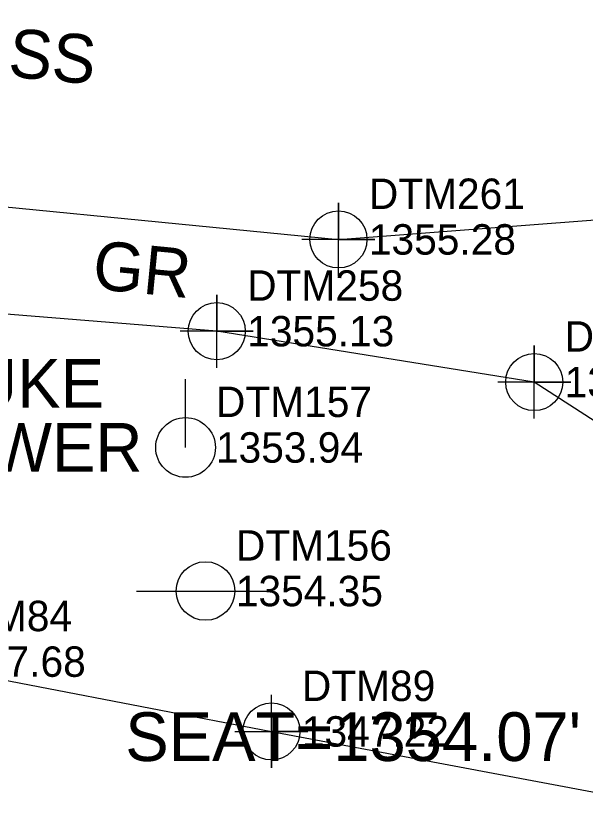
# Model space of a CAD drawing. Extents: x 1251492 to 1253015, y 859607 to 860610.
# Drawn here: x 1251972.9 to 1252019.6, y 860040 to 860105 of the extents above; entities that cross this region are included whole.
import ezdxf

# ---------------------------------------------------------------- set-up
doc = ezdxf.new("R2010")
doc.units = 0
for name, color, linetype in [('Exist Hydro Jurisdictional Stream or Body of Water', 7, 'Continuous'), ('Exist Hydro Stream or Body of Water Cogo Elevation', 7, 'Continuous'), ('Exist Hydro Stream or Body of Water Cogo Number', 7, 'Continuous'), ('Exist Hydro Stream or Body of Water Cogo Point CELL', 7, 'Continuous'), ('Exist Roads Soil', 7, 'Continuous'), ('Exist Roads Soil Cogo Elevation', 7, 'Continuous'), ('Exist Roads Soil Cogo Number', 7, 'Continuous'), ('Exist Roads Soil Cogo Point CELL', 7, 'Continuous'), ('Exist Roads Soil Text', 7, 'Continuous'), ('Exist Structure Major Bridge Seat Top Elevation', 7, 'Continuous'), ('Exist Utilities Power Pole CELL', 7, 'Continuous'), ('Exist Utilities Power Pole Cogo Elevation', 7, 'Continuous'), ('Exist Utilities Power Pole Cogo Number', 7, 'Continuous'), ('Exist Utilities Power Pole Text', 7, 'Continuous'), ('Exist Utilities Telephone Pole CELL', 7, 'Continuous'), ('Exist Utilities Telephone Pole Cogo Elevation', 7, 'Continuous'), ('Exist Utilities Telephone Pole Cogo Number', 7, 'Continuous'), ('Exist Vegetation Woods Line Text', 7, 'Continuous')]:
    doc.layers.add(name, color=color, linetype=linetype)

msp = doc.modelspace()

# ---------------------------------------------------------------- linework, layer by layer
at = {"layer": 'Exist Hydro Jurisdictional Stream or Body of Water'}
msp.add_lwpolyline([(1251931.145, 860058.535), (1251964.012, 860051.945), (1251993.851, 860046.208), (1252023.877, 860040.562), (1252026.116, 860039.985)], dxfattribs=at)
at = {"layer": 'Exist Hydro Stream or Body of Water Cogo Point CELL'}
msp.add_lwpolyline([(1251990.851, 860046.208), (1251996.851, 860046.208), (1251993.851, 860046.208), (1251993.851, 860043.208), (1251993.851, 860049.208)], dxfattribs=at)
msp.add_circle((1251993.851, 860046.208), 2.344, dxfattribs=at)
at = {"layer": 'Exist Roads Soil'}
for points in [[(1251956.92, 860090.785), (1251999.355, 860086.635), (1252028.297, 860088.86), (1252043.486, 860095.855), (1252053.212, 860097.101)], [(1252027.154, 860067.333), (1252015.44, 860074.915), (1251989.358, 860079.095), (1251956.453, 860081.754)]]:
    msp.add_lwpolyline(points, dxfattribs=at)
at = {"layer": 'Exist Roads Soil Cogo Point CELL'}
for points in [[(1251999.355, 860083.635), (1251999.355, 860089.635), (1251999.355, 860086.635), (1252002.355, 860086.635), (1251996.355, 860086.635)], [(1251989.358, 860076.095), (1251989.358, 860082.095), (1251989.358, 860079.095), (1251992.358, 860079.095), (1251986.358, 860079.095)], [(1252015.44, 860071.915), (1252015.44, 860077.915), (1252015.44, 860074.915), (1252018.44, 860074.915), (1252012.44, 860074.915)]]:
    msp.add_lwpolyline(points, dxfattribs=at)
for centre in [(1251999.355, 860086.635), (1251989.358, 860079.095), (1252015.44, 860074.915)]:
    msp.add_circle(centre, 2.344, dxfattribs=at)
at = {"layer": 'Exist Utilities Power Pole CELL'}
for q in [(1251986.794, 860075.165), (1251986.794, 860069.54)]:
    msp.add_line((1251986.794, 860069.54), q, dxfattribs=at)
msp.add_circle((1251986.794, 860069.54), 2.45, dxfattribs=at)
at = {"layer": 'Exist Utilities Telephone Pole CELL'}
for p, q in [((1251982.755, 860057.745), (1251994.093, 860057.745)), ((1251988.43, 860057.745), (1251988.43, 860057.745))]:
    msp.add_line(p, q, dxfattribs=at)
msp.add_circle((1251988.43, 860057.745), 2.407, dxfattribs=at)

# ---------------------------------------------------------------- texts
at = {"layer": 'Exist Hydro Stream or Body of Water Cogo Elevation'}
for s, p in [('1347.68', (1251966.512, 860050.695)), ('1347.22', (1251996.351, 860044.958))]:
    msp.add_text(s, height=2.5, dxfattribs=at).set_placement(p)
at = {"layer": 'Exist Hydro Stream or Body of Water Cogo Number'}
for s, p in [('DTM84', (1251966.512, 860054.445)), ('DTM89', (1251996.351, 860048.708))]:
    msp.add_text(s, height=2.5, dxfattribs=at).set_placement(p)
at = {"layer": 'Exist Roads Soil Cogo Elevation'}
for s, p in [('1355.28', (1252001.855, 860085.385)), ('1355.13', (1251991.858, 860077.845)), ('1356.25', (1252017.94, 860073.665))]:
    msp.add_text(s, height=2.5, dxfattribs=at).set_placement(p)
at = {"layer": 'Exist Roads Soil Cogo Number'}
for s, p in [('DTM261', (1252001.855, 860089.135)), ('DTM258', (1251991.858, 860081.595)), ('DTM257', (1252017.94, 860077.415))]:
    msp.add_text(s, height=2.5, dxfattribs=at).set_placement(p)
at = {"layer": 'Exist Roads Soil Text'}
msp.add_text('GR', height=4, rotation=354.41443, dxfattribs=at).set_placement((1251979.052, 860082.592))
at = {"layer": 'Exist Structure Major Bridge Seat Top Elevation'}
msp.add_text("SEAT=1354.07'", height=4, dxfattribs=at).set_placement((1251981.841, 860043.779))
at = {"layer": 'Exist Utilities Power Pole Cogo Elevation'}
msp.add_text('1353.94', height=2.5, dxfattribs=at).set_placement((1251989.294, 860068.29))
at = {"layer": 'Exist Utilities Power Pole Cogo Number'}
msp.add_text('DTM157', height=2.5, dxfattribs=at).set_placement((1251989.294, 860072.04))
at = {"layer": 'Exist Utilities Power Pole Text'}
for s, p in [('DUKE', (1251965.237, 860072.798)), ('POWER', (1251963.048, 860067.548))]:
    msp.add_text(s, height=4, dxfattribs=at).set_placement(p)
at = {"layer": 'Exist Utilities Telephone Pole Cogo Elevation'}
msp.add_text('1354.35', height=2.5, dxfattribs=at).set_placement((1251990.93, 860056.495))
at = {"layer": 'Exist Utilities Telephone Pole Cogo Number'}
msp.add_text('DTM156', height=2.5, dxfattribs=at).set_placement((1251990.93, 860060.245))
at = {"layer": 'Exist Vegetation Woods Line Text'}
msp.add_text('GRASS', height=4, rotation=354.7669, dxfattribs=at).set_placement((1251960.593, 860101.075))

doc.saveas('drawing.dxf')
